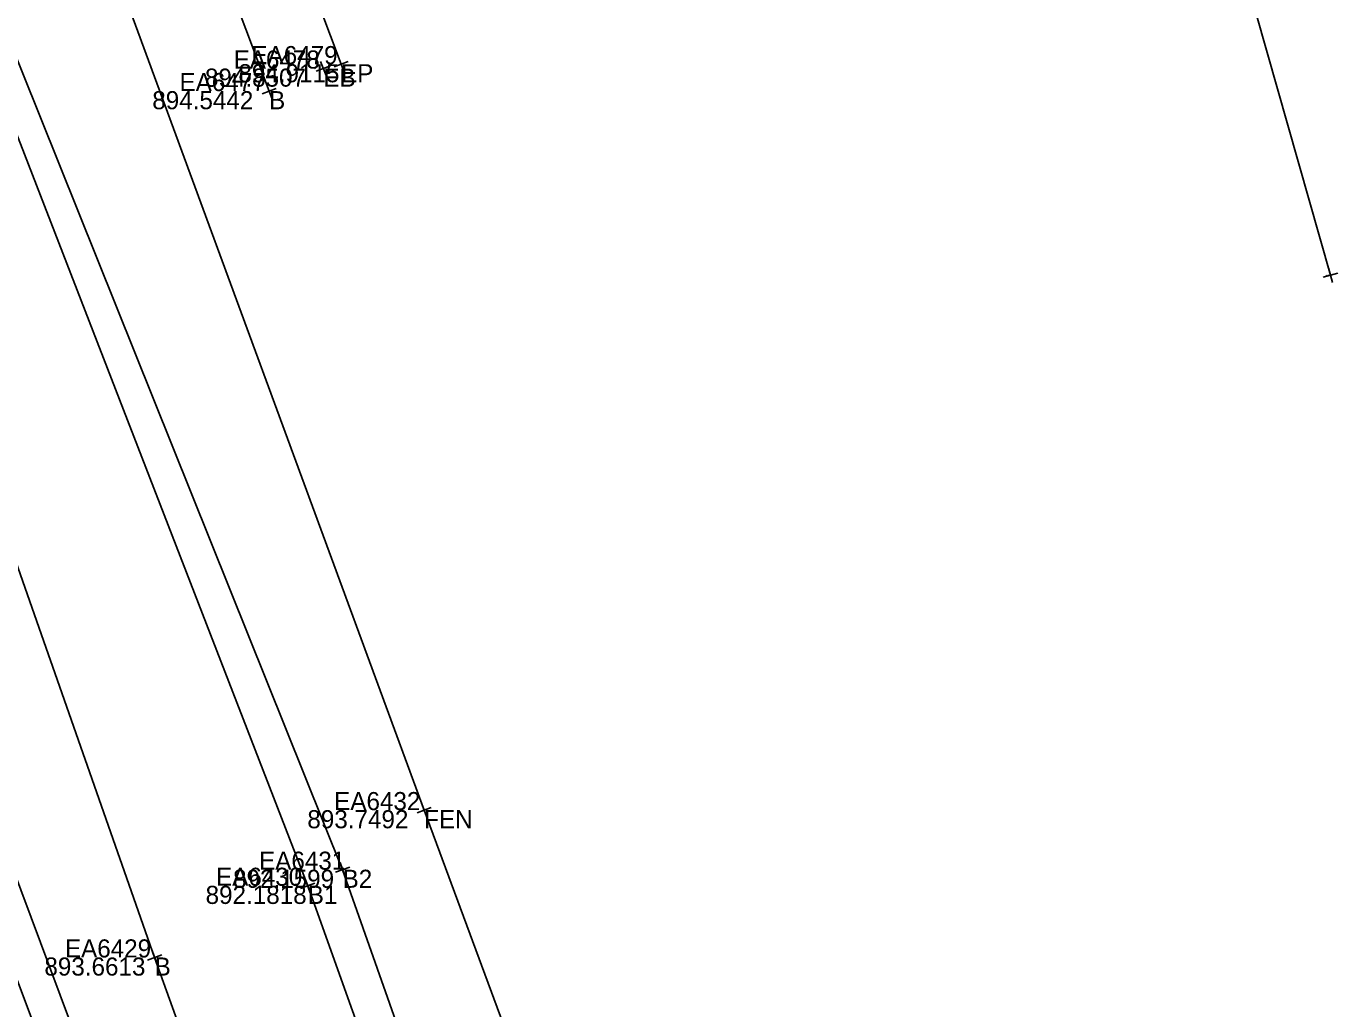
# Model space of a CAD drawing. Extents: x 179044 to 189691, y 286531 to 301257.
# Drawn here: x 180404.1 to 180491, y 300399.8 to 300464.9 of the extents above; entities that cross this region are included whole.
import ezdxf

# ---------------------------------------------------------------- set-up
doc = ezdxf.new("R2010")
doc.units = 0
for name, color, linetype in [('PV_X_EOP', 7, 'Continuous'), ('PV_X_Shoulder_Aggregate', 7, 'Continuous'), ('RD_X_Fence', 7, 'Continuous'), ('SV_X_Break_Lines', 7, 'Continuous'), ('SV_X_Shot_Marker', 7, 'Continuous'), ('SV_X_Text_Comment', 7, 'Continuous'), ('SV_X_Text_Elevation', 7, 'Continuous'), ('SV_X_Text_Name', 7, 'Continuous'), ('UT_X_Gas', 7, 'Continuous')]:
    doc.layers.add(name, color=color, linetype=linetype)

msp = doc.modelspace()

# ---------------------------------------------------------------- linework, layer by layer
at = {"layer": 'PV_X_EOP'}
for points in [[(180395.237, 300541.249), (180424.935, 300462.361)], [(180439.123, 300306.816), (180406.158, 300394.554), (180372.027, 300485.65), (180354.793, 300532.586)]]:
    msp.add_lwpolyline(points, dxfattribs=at)
at = {"layer": 'PV_X_Shoulder_Aggregate'}
msp.add_lwpolyline([(180440.928, 300307.719), (180408.311, 300395.34), (180374.353, 300486.274)], dxfattribs=at)
at = {"layer": 'RD_X_Fence'}
msp.add_lwpolyline([(180464.887, 300319.769), (180430.439, 300412.925), (180399.729, 300496.442)], dxfattribs=at)
at = {"layer": 'SV_X_Break_Lines'}
for points in [[(180397.947, 300519.64), (180420.167, 300460.574)], [(180455.61, 300315.867), (180422.725, 300407.911), (180389.992, 300492.479)], [(180457.481, 300316.825), (180425.036, 300408.977), (180391.243, 300493.136)], [(180445.855, 300310.712), (180412.585, 300403.162), (180382.397, 300489.36)]]:
    msp.add_lwpolyline(points, dxfattribs=at)
at = {"layer": 'SV_X_Shot_Marker'}
for p, q in [((180424.226, 300462.25), (180423.293, 300461.89)), ((180423.579, 300462.536), (180423.939, 300461.604)), ((180423.759, 300462.07), (180423.759, 300462.07)), ((180425.403, 300462.537), (180424.467, 300462.185)), ((180424.759, 300462.829), (180425.111, 300461.893)), ((180424.935, 300462.361), (180424.935, 300462.361)), ((180420.635, 300460.75), (180419.699, 300460.398)), ((180419.991, 300461.042), (180420.343, 300460.106)), ((180420.167, 300460.574), (180420.167, 300460.574)), ((180489.991, 300448.24), (180490.953, 300448.513)), ((180490.609, 300447.895), (180490.335, 300448.857)), ((180490.472, 300448.376), (180490.472, 300448.376)), ((180430.613, 300412.456), (180430.266, 300413.394)), ((180429.97, 300412.752), (180430.908, 300413.099)), ((180430.439, 300412.925), (180430.439, 300412.925)), ((180424.564, 300408.811), (180425.508, 300409.143)), ((180425.202, 300408.505), (180424.87, 300409.449)), ((180422.893, 300407.441), (180422.556, 300408.382)), ((180425.036, 300408.977), (180425.036, 300408.977)), ((180422.254, 300407.743), (180423.196, 300408.08)), ((180422.725, 300407.911), (180422.725, 300407.911)), ((180412.115, 300402.992), (180413.056, 300403.331)), ((180412.755, 300402.691), (180412.416, 300403.632)), ((180412.585, 300403.162), (180412.585, 300403.162))]:
    msp.add_line(p, q, dxfattribs=at)
at = {"layer": 'UT_X_Gas'}
msp.add_lwpolyline([(180490.472, 300448.376), (180476.391, 300497.947), (180471.56, 300513.097), (180457.102, 300544.929), (180444.552, 300576.645), (180429.401, 300607.116), (180413.672, 300639.281), (180388.523, 300702.941)], dxfattribs=at)

# ---------------------------------------------------------------- texts
at = {"layer": 'SV_X_Text_Comment'}
for s, height, p in [('EB', 1.2, (180423.759, 300460.87)), ('EP', 1.2, (180424.935, 300461.161)), ('B', 1.2, (180420.167, 300459.374)), ('GL', 0.06, (180490.472, 300448.316)), ('FEN', 1.2, (180430.439, 300411.725)), ('B2', 1.2, (180425.036, 300407.777)), ('B1', 1.2, (180422.725, 300406.711)), ('B', 1.2, (180412.585, 300401.962))]:
    msp.add_text(s, height=height, dxfattribs=at).set_placement(p)
at = {"layer": 'SV_X_Text_Elevation'}
for s, height, p in [('894.8507', 1.2, (180415.917, 300460.87)), ('894.9115', 1.2, (180418.133, 300461.161)), ('894.5442', 1.2, (180412.429, 300459.374)), ('894.1190', 0.06, (180490.127, 300448.316)), ('893.7492', 1.2, (180422.701, 300411.725)), ('892.1599', 1.2, (180417.78, 300407.777)), ('892.1818', 1.2, (180415.961, 300406.711)), ('893.6613', 1.2, (180405.283, 300401.962))]:
    msp.add_text(s, height=height, dxfattribs=at).set_placement(p)
at = {"layer": 'SV_X_Text_Name'}
for s, height, p in [('EA6478', 1.2, (180417.816, 300462.07)), ('EA6479', 1.2, (180418.992, 300462.361)), ('EA6477', 1.2, (180414.234, 300460.574)), ('SV5034', 0.06, (180490.168, 300448.376)), ('EA6432', 1.2, (180424.477, 300412.925)), ('EA6431', 1.2, (180419.503, 300408.977)), ('EA6430', 1.2, (180416.65, 300407.911)), ('EA6429', 1.2, (180406.643, 300403.162))]:
    msp.add_text(s, height=height, dxfattribs=at).set_placement(p)

doc.saveas('drawing.dxf')
